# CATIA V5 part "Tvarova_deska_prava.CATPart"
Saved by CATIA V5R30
Part number: Tvarova_deska_prava
Definition: F 50_346446_46_1730
Nomenclature: F 50_346446_46_1730
Source: Unknown
Description: PART--DESC
Bounding box of the stored display mesh (mm): x -223 to 223, y -173 to 173, z -46 to 0
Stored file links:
  E:\Bakalarka\Model\Forma_v7\Tvarova_deska_prava.CATPart
  E:\Bakalarka\Model\Forma_v7\Vstrikovaci_cast.CATProduct
  E:\Bakalarka\Model\Forma_v7\Forma_Vstrikovaci_cast.CATPart
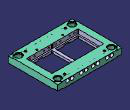
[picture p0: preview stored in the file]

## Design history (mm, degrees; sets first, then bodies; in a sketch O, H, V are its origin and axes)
Body1 "MANIFOLD_SOLID_BREP #4131" (main body)
  Solid1: solid without history
  DatumSurface1
  Sketch1 on face of Solid1, origin (0, 0, 0), H (1, 0, 0), V (0, 1, 0)
  Pocket1: profile Sketch1, direction (0, 0, -1), length 30
  Mirror1: of Pocket1, about yz-plane
  DatumCurve1 to DatumCurve9
  Sketch2 on face of Solid1, origin (0, 0, -46), H (1, 0, 0), V (0, -1, 0)
    projected line E1 (-170, 75) -> (-170, -75) from edge of DatumCurve1
    projected arc E2 centre (-165, -75) radius 5 from (-170, -75) to (-165, -80) ccw from edge of DatumCurve2
    projected line E3 (-165, -80) -> (-15, -80) from edge of DatumCurve3
    projected arc E4 centre (-15, -75) radius 5 from (-15, -80) to (-10, -75) ccw from edge of DatumCurve4
    projected line E5 (-10, -75) -> (-10, 75) from edge of DatumCurve5
    projected arc E6 centre (-15, 75) radius 5 from (-10, 75) to (-15, 80) ccw from edge of DatumCurve6
    projected line E7 (-15, 80) -> (-73.5, 80) from edge of DatumCurve7
    projected line E8 (-106.5, 80) -> (-165, 80) from edge of DatumCurve8
    projected arc E9 centre (-165, 75) radius 5 from (-165, 80) to (-170, 75) ccw from edge of DatumCurve9
    line L1 (-106.5, 80) -> (-73.5, 80)
    horizontal: L1 H
  Pocket2: profile Sketch2, direction (0, 0, 1), length 16
  Mirror2: of Pocket2, about yz-plane
  Fillet1: radius 1, on edge [face of Pocket1 | face of Mirror1]
  Fillet2: radius 1, on edge [face of Mirror1 | face of Pocket1]
  DatumCurve10 to DatumCurve12
  DatumSurface2
  DatumSurface3
  Sketch3 on face of Solid1, origin (0, 0, -46), H (1, 0, 0), V (0, -1, 0)
    line L1 (106, 80) -> (74, 80)
    line L2 (74, 80) -> (74, 113)
    line L3 (74, 113) -> (106, 113)
    line L4 (106, 113) -> (106, 80)
    reference projected line E1 (106, 80.5) -> (106, 89.5) from edge of DatumCurve12
    reference projected line E2 (106.5, 80) -> (165, 80) from edge [face of Mirror2 | face of Solid1]
    reference intersected line E3 (74.5, 105) -> (105.5, 105) from face of DatumSurface2
    reference intersected line E4 (74, 80.366) -> (74, 104.5) from face of DatumSurface3
    distance L4 E1 = 0
    distance L1 E2 = 0
    distance L3 E3 = 8
    distance L2 E4 = 0
    horizontal: L1 H, L3 H
    vertical: L2 V, L4 V
  Pocket3: profile Sketch3, direction (0, 0, 1), length 6
  Fillet3: radius 0.5, on edge [face of Pocket3 from Sketch3.L4 | end face of Pocket3]; face of Pocket3 from Sketch3.L4; face of Pocket3 from Sketch3.L3; end face of Pocket3; face of Pocket3 from Sketch3.L2
  Mirror3: of Pocket3, about yz-plane
  Fillet4: radius 0.5, on face of Mirror3 (x3); edge [face of Mirror3 | face of Solid1]
  Body2
    Solid2: solid without history
  Remove1: tool Body2
  Body3
  Remove2: tool Body3
  DatumCurve13 to DatumCurve28
  Sketch4 on face of Solid1, origin (0, 173, 0), H (-1, 0, 0), V (0, 0, 1)
    point P1 (-154.5, -14)
    point P2 (-122.5, -14)
    point P3 (-56.5, -14)
    point P4 (-24.5, -14)
    point P5 (25.5, -14)
    point P6 (57.5, -14)
    point P7 (123.5, -14)
    point P8 (155.5, -14)
    construction circle A1 centre (155.5, -14) radius 3
    construction circle A2 centre (123.5, -14) radius 3
    construction circle A3 centre (57.5, -14) radius 3
    construction circle A4 centre (25.5, -14) radius 3
    construction circle A5 centre (-24.5, -14) radius 3
    construction circle A6 centre (-56.5, -14) radius 3
    construction circle A7 centre (-122.5, -14) radius 3
    construction circle A8 centre (-154.5, -14) radius 3
    concentricity: P1 A8, P2 A7, P3 A6, P4 A5, P5 A4, P6 A3, P7 A2, P8 A1
  Sketch5 on face of Solid1, origin (0, -173, 0), H (1, 0, 0), V (0, 0, 1)
    projected point E1 (154.5, -14) from Sketch4.P1
    projected point E2 (122.5, -14) from Sketch4.P2
    projected point E3 (56.5, -14) from Sketch4.P3
    projected point E4 (24.5, -14) from Sketch4.P4
    projected point E5 (-25.5, -14) from Sketch4.P5
    projected point E6 (-57.5, -14) from Sketch4.P6
    projected point E7 (-123.5, -14) from Sketch4.P7
    projected point E8 (-155.5, -14) from Sketch4.P8
  DatumCurve29 to DatumCurve33
  DatumSurface4
  Sketch6 on face of Solid1, origin (0, 173, 0), H (-1, 0, 0), V (0, 0, 1)
    point P1 (155, -14)
    point P2 (123, -14)
    point P3 (57, -14)
    point P4 (25, -14)
    point P5 (-25, -14)
    point P6 (-57, -14)
    point P7 (-123, -14)
    point P8 (-155, -14)
    reference projected line E1 (223, 0) -> (-223, 0) from edge of DatumCurve29
    reference projected line E2 (-189, 0) -> (189, 0) from edge [face of Solid1 | face of Solid1]
    reference projected line E3 (223, 0) -> (-223, 0) from edge of DatumCurve30
    reference projected line E4 (223, 0) -> (-223, 0) from edge of DatumCurve31
    reference projected line E5 (223, 0) -> (-223, 0) from edge of DatumCurve32
    reference projected line E6 (223, 0) -> (-223, 0) from edge of DatumCurve33
    reference intersected curve E7 from face of DatumSurface4
    reference projected line E8 (223, -4) -> (223, -46) from edge [face of Solid1 | face of Solid1]
    distance P8 E1 = 14
    distance P7 E2 = 14
    distance P6 E3 = 14
    distance P5 E4 = 14
    distance P4 E5 = 14
    distance P3 E2 = 14
    distance P2 E6 = 14
    distance P1 E7 = 14
    distance P1 E8 = 68
    distance P2 P1 = 32
    distance P2 P3 = 66
    distance P3 P4 = 32
    distance P4 P5 = 50
    distance P5 P6 = 32
    distance P7 P6 = 66
    distance P7 P8 = 32
  Sketch7 on face of Solid1, origin (155, 173, -14), H (1, 0, 0), V (0, 0, -1)
    point P1 (0, 0)
    reference projected point E1 (0, 0) from Sketch6.P8
    coincidence: E1 P1
  Hole1: placed by Sketch7, at (155, 173, -14) direction (0, -1, 0), diameter 10, depth 500, V-bottom angle 120
  Sketch8 on face of Solid1, origin (123, 173, -14), H (1, 0, 0), V (0, 0, -1)
    point P1 (0, 0)
    reference projected point E1 (0, 0) from Sketch6.P7
    coincidence: E1 P1
  Hole2: placed by Sketch8, at (123, 173, -14) direction (0, -1, 0), diameter 10, depth 500, V-bottom angle 120
  Sketch9 on face of Solid1, origin (57, 173, -14), H (1, 0, 0), V (0, 0, -1)
    point P1 (0, 0)
    reference projected point E1 (0, 0) from Sketch6.P6
    coincidence: E1 P1
  Hole3: placed by Sketch9, at (57, 173, -14) direction (0, -1, 0), diameter 10, depth 500, V-bottom angle 120
  Sketch10 on face of Solid1, origin (25, 173, -14), H (1, 0, 0), V (0, 0, -1)
    point P1 (0, 0)
    reference projected point E1 (0, 0) from Sketch6.P5
    coincidence: E1 P1
  Hole4: placed by Sketch10, at (25, 173, -14) direction (0, -1, 0), diameter 10, depth 500, V-bottom angle 120
  Sketch11 on face of Solid1, origin (-25, 173, -14), H (1, 0, 0), V (0, 0, -1)
    point P1 (0, 0)
    reference projected point E1 (0, 0) from Sketch6.P4
    coincidence: E1 P1
  Hole5: placed by Sketch11, at (-25, 173, -14) direction (0, -1, 0), diameter 10, depth 500, V-bottom angle 120
  Sketch12 on face of Solid1, origin (-57, 173, -14), H (1, 0, 0), V (0, 0, -1)
    point P1 (0, 0)
    reference projected point E1 (0, 0) from Sketch6.P3
    coincidence: E1 P1
  Hole6: placed by Sketch12, at (-57, 173, -14) direction (0, -1, 0), diameter 10, depth 500, V-bottom angle 120
  Sketch13 on face of Solid1, origin (-123, 173, -14), H (1, 0, 0), V (0, 0, -1)
    point P1 (0, 0)
    reference projected point E1 (0, 0) from Sketch6.P2
    coincidence: E1 P1
  Hole7: placed by Sketch13, at (-123, 173, -14) direction (0, -1, 0), diameter 10, depth 500, V-bottom angle 120
  Sketch14 on face of Solid1, origin (-155, 173, -14), H (1, 0, 0), V (0, 0, -1)
    point P1 (0, 0)
    reference projected point E1 (0, 0) from Sketch6.P1
    coincidence: E1 P1
  Hole8: placed by Sketch14, at (-155, 173, -14) direction (0, -1, 0), diameter 10, depth 500, V-bottom angle 120
  Sketch15 on face of Solid1, origin (-155, 173, -14), H (1, 0, 0), V (0, 0, -1)
    point P1 (0, 0)
    reference projected point E1 (0, 0) from Sketch6.P1
    coincidence: E1 P1
  Hole9: placed by Sketch15, at (-155, 173, -14) direction (0, -1, 0), diameter 12.376, depth 12, V-bottom angle 120, threaded "M14x1.5", thread diameter 14, thread depth 10, pitch 1.5
  Sketch16 on face of Solid1, origin (-123, 173, -14), H (1, 0, 0), V (0, 0, -1)
    point P1 (0, 0)
    reference projected point E1 (0, 0) from Sketch6.P2
    coincidence: E1 P1
  Hole10: placed by Sketch16, at (-123, 173, -14) direction (0, -1, 0), diameter 12.376, depth 12, V-bottom angle 120, threaded "M14x1.5", thread diameter 14, thread depth 10, pitch 1.5
  Sketch17 on face of Solid1, origin (-57, 173, -14), H (1, 0, 0), V (0, 0, -1)
    point P1 (0, 0)
    reference projected point E1 (0, 0) from Sketch6.P3
    coincidence: E1 P1
  Hole11: placed by Sketch17, at (-57, 173, -14) direction (0, -1, 0), diameter 12.376, depth 12, V-bottom angle 120, threaded "M14x1.5", thread diameter 14, thread depth 10, pitch 1.5
  Sketch18 on face of Solid1, origin (-25, 173, -14), H (1, 0, 0), V (0, 0, -1)
    point P1 (0, 0)
    reference projected point E1 (0, 0) from Sketch6.P4
    coincidence: E1 P1
  Hole12: placed by Sketch18, at (-25, 173, -14) direction (0, -1, 0), diameter 12.376, depth 12, V-bottom angle 120, threaded "M14x1.5", thread diameter 14, thread depth 10, pitch 1.5
  Sketch19 on face of Solid1, origin (25, 173, -14), H (1, 0, 0), V (0, 0, -1)
    point P1 (0, 0)
    reference projected point E1 (0, 0) from Sketch6.P5
    coincidence: E1 P1
  Hole13: placed by Sketch19, at (25, 173, -14) direction (0, -1, 0), diameter 12.376, depth 12, V-bottom angle 120, threaded "M14x1.5", thread diameter 14, thread depth 10, pitch 1.5
  Sketch20 on face of Solid1, origin (57, 173, -14), H (1, 0, 0), V (0, 0, -1)
    point P1 (0, 0)
    reference projected point E1 (0, 0) from Sketch6.P6
    coincidence: E1 P1
  Hole14: placed by Sketch20, at (57, 173, -14) direction (0, -1, 0), diameter 12.376, depth 12, V-bottom angle 120, threaded "M14x1.5", thread diameter 14, thread depth 10, pitch 1.5
  Sketch21 on face of Solid1, origin (155, 173, -14), H (1, 0, 0), V (0, 0, -1)
    point P1 (0, 0)
    reference projected point E1 (0, 0) from Sketch6.P8
    coincidence: E1 P1
  Hole15: placed by Sketch21, at (155, 173, -14) direction (0, -1, 0), diameter 12.376, depth 12, V-bottom angle 120, threaded "M14x1.5", thread diameter 14, thread depth 10, pitch 1.5
  Sketch22 on face of Solid1, origin (123, 173, -14), H (1, 0, 0), V (0, 0, -1)
    point P1 (0, 0)
    reference projected point E1 (0, 0) from Sketch6.P7
    coincidence: E1 P1
  Hole16: placed by Sketch22, at (123, 173, -14) direction (0, -1, 0), diameter 12.376, depth 12, V-bottom angle 120, threaded "M14x1.5", thread diameter 14, thread depth 10, pitch 1.5
  Sketch23 on face of Solid1, origin (0, -173, 0), H (1, 0, 0), V (0, 0, 1)
    projected point E1 (155, -14) from Sketch6.P8
    projected point E2 (123, -14) from Sketch6.P7
    projected point E3 (57, -14) from Sketch6.P6
    projected point E4 (25, -14) from Sketch6.P5
    projected point E5 (-25, -14) from Sketch6.P4
    projected point E6 (-57, -14) from Sketch6.P3
    projected point E7 (-123, -14) from Sketch6.P2
    projected point E8 (-155, -14) from Sketch6.P1
  Sketch24 on face of Solid1, origin (-155, -173, -14), H (1, 0, 0), V (0, 0, 1)
    point P1 (0, 0)
    reference projected point E1 (0, 0) from vertex of Sketch23.E8
    coincidence: E1 P1
  Hole17: placed by Sketch24, at (-155, -173, -14) direction (0, 1, 0), diameter 12.376, depth 12, V-bottom angle 120, threaded "M14x1.5", thread diameter 14, thread depth 10, pitch 1.5
  Sketch25 on face of Solid1, origin (-123, -173, -14), H (1, 0, 0), V (0, 0, 1)
    point P1 (0, 0)
    reference projected point E1 (0, 0) from vertex of Sketch23.E7
    coincidence: E1 P1
  Hole18: placed by Sketch25, at (-123, -173, -14) direction (0, 1, 0), diameter 12.376, depth 12, V-bottom angle 120, threaded "M14x1.5", thread diameter 14, thread depth 10, pitch 1.5
  Sketch26 on face of Solid1, origin (-57, -173, -14), H (1, 0, 0), V (0, 0, 1)
    point P1 (0, 0)
    reference projected point E1 (0, 0) from vertex of Sketch23.E6
    coincidence: E1 P1
  Hole19: placed by Sketch26, at (-57, -173, -14) direction (0, 1, 0), diameter 12.376, depth 12, V-bottom angle 120, threaded "M14x1.5", thread diameter 14, thread depth 10, pitch 1.5
  Sketch27 on face of Solid1, origin (-25, -173, -14), H (1, 0, 0), V (0, 0, 1)
    point P1 (0, 0)
    reference projected point E1 (0, 0) from vertex of Sketch23.E5
    coincidence: E1 P1
  Hole20: placed by Sketch27, at (-25, -173, -14) direction (0, 1, 0), diameter 12.376, depth 12, V-bottom angle 120, threaded "M14x1.5", thread diameter 14, thread depth 10, pitch 1.5
  Sketch28 on face of Solid1, origin (25, -173, -14), H (1, 0, 0), V (0, 0, 1)
    point P1 (0, 0)
    reference projected point E1 (0, 0) from vertex of Sketch23.E4
    coincidence: E1 P1
  Hole21: placed by Sketch28, at (25, -173, -14) direction (0, 1, 0), diameter 12.376, depth 12, V-bottom angle 120, threaded "M14x1.5", thread diameter 14, thread depth 10, pitch 1.5
  Sketch29 on face of Solid1, origin (57, -173, -14), H (1, 0, 0), V (0, 0, 1)
    point P1 (0, 0)
    reference projected point E1 (0, 0) from vertex of Sketch23.E3
    coincidence: E1 P1
  Hole22: placed by Sketch29, at (57, -173, -14) direction (0, 1, 0), diameter 12.376, depth 12, V-bottom angle 120, threaded "M14x1.5", thread diameter 14, thread depth 10, pitch 1.5
  Sketch30 on face of Solid1, origin (123, -173, -14), H (1, 0, 0), V (0, 0, 1)
    point P1 (0, 0)
    reference projected point E1 (0, 0) from vertex of Sketch23.E2
    coincidence: E1 P1
  Hole23: placed by Sketch30, at (123, -173, -14) direction (0, 1, 0), diameter 12.376, depth 12, V-bottom angle 120, threaded "M14x1.5", thread diameter 14, thread depth 10, pitch 1.5
  Sketch31 on face of Solid1, origin (155, -173, -14), H (1, 0, 0), V (0, 0, 1)
    point P1 (0, 0)
    reference projected point E1 (0, 0) from vertex of Sketch23.E1
    coincidence: E1 P1
  Hole24: placed by Sketch31, at (155, -173, -14) direction (0, 1, 0), diameter 12.376, depth 12, V-bottom angle 120, threaded "M14x1.5", thread diameter 14, thread depth 10, pitch 1.5
  Sketch32 on face of Solid1, origin (0, -173, 0), H (1, 0, 0), V (0, 0, 1)
    circle A1 centre (155, -14) radius 12.5
    point P1 (155, -14)
    circle A2 centre (123, -14) radius 12.5
    circle A3 centre (57, -14) radius 12.5
    circle A4 centre (25, -14) radius 12.5
    circle A5 centre (-25, -14) radius 12.5
    circle A6 centre (-57, -14) radius 12.5
    circle A7 centre (-123, -14) radius 12.5
    circle A8 centre (-155, -14) radius 12.5
    reference projected line E1 (-189, 0) -> (189, 0) from edge [face of Solid1 | face of Solid1]
    reference projected line E2 (-223, -4) -> (-223, -42) from edge [face of Solid1 | face of Solid1]
    radius A8 = 12.5
    radius A7 = 12.5
    radius A6 = 12.5
    radius A5 = 12.5
    radius A4 = 12.5
    radius A3 = 12.5
    radius A2 = 12.5
    radius A1 = 12.5
    distance P1 E1 = 14
    distance A2 E1 = 1.5
    distance A3 E1 = 26.5
    distance A4 E1 = 1.5
    distance A5 E1 = 26.5
    distance A6 E1 = 1.5
    distance A7 E1 = 1.5
    distance A8 E1 = 26.5
    distance A8 E2 = 80.5
    distance A7 A8 = 7
    distance A6 A7 = 41
    distance A5 A6 = 7
    distance A5 A4 = 50
    distance A3 A4 = 7
    distance A3 A2 = 66
    distance A2 A1 = 32
  Pocket4: profile Sketch32, direction (0, 1, 0), length 25
  Mirror4: of Pocket4, about zx-plane
  Sketch33 on face of Mirror4, origin (0, 148, 0), H (-1, 0, 0), V (0, 0, 1)
    projected point E1 (-155, -14) from vertex of Sketch23.E1
    projected point E2 (-123, -14) from vertex of Sketch23.E2
    projected point E3 (-57, -14) from vertex of Sketch23.E3
    projected point E4 (-25, -14) from vertex of Sketch23.E4
    projected point E5 (25, -14) from vertex of Sketch23.E5
    projected point E6 (57, -14) from vertex of Sketch23.E6
    projected point E7 (123, -14) from vertex of Sketch23.E7
    projected point E8 (155, -14) from vertex of Sketch23.E8
  Sketch34 on face of Mirror4, origin (-155, 148, -14), H (1, 0, 0), V (0, 0, -1)
    point P1 (0, 0)
    reference projected point E1 (0, 0) from vertex of Sketch33.E8
    coincidence: E1 P1
  Hole25: placed by Sketch34, at (-155, 148, -14) direction (0, -1, 0), diameter 12.376, depth 12, V-bottom angle 120, threaded "M14x1.5", thread diameter 14, thread depth 10, pitch 1.5
  Sketch35 on face of Mirror4, origin (-123, 148, -14), H (1, 0, 0), V (0, 0, -1)
    point P1 (0, 0)
    reference projected point E1 (0, 0) from vertex of Sketch33.E7
    coincidence: E1 P1
  Hole26: placed by Sketch35, at (-123, 148, -14) direction (0, -1, 0), diameter 12.376, depth 12, V-bottom angle 120, threaded "M14x1.5", thread diameter 14, thread depth 10, pitch 1.5
  Sketch36 on face of Mirror4, origin (-57, 148, -14), H (1, 0, 0), V (0, 0, -1)
    point P1 (0, 0)
    reference projected point E1 (0, 0) from vertex of Sketch33.E6
    coincidence: E1 P1
  Hole27: placed by Sketch36, at (-57, 148, -14) direction (0, -1, 0), diameter 12.376, depth 12, V-bottom angle 120, threaded "M14x1.5", thread diameter 14, thread depth 10, pitch 1.5
  Sketch37 on face of Mirror4, origin (-25, 148, -14), H (1, 0, 0), V (0, 0, -1)
    point P1 (0, 0)
    reference projected point E1 (0, 0) from vertex of Sketch33.E5
    coincidence: E1 P1
  Hole28: placed by Sketch37, at (-25, 148, -14) direction (0, -1, 0), diameter 12.376, depth 12, V-bottom angle 120, threaded "M14x1.5", thread diameter 14, thread depth 10, pitch 1.5
  Sketch38 on face of Mirror4, origin (25, 148, -14), H (1, 0, 0), V (0, 0, -1)
    point P1 (0, 0)
    reference projected point E1 (0, 0) from vertex of Sketch33.E4
    coincidence: E1 P1
  Hole29: placed by Sketch38, at (25, 148, -14) direction (0, -1, 0), diameter 12.376, depth 12, V-bottom angle 120, threaded "M14x1.5", thread diameter 14, thread depth 10, pitch 1.5
  Sketch39 on face of Mirror4, origin (57, 148, -14), H (1, 0, 0), V (0, 0, -1)
    point P1 (0, 0)
    reference projected point E1 (0, 0) from vertex of Sketch33.E3
    coincidence: E1 P1
  Hole30: placed by Sketch39, at (57, 148, -14) direction (0, -1, 0), diameter 12.376, depth 12, V-bottom angle 120, threaded "M14x1.5", thread diameter 14, thread depth 10, pitch 1.5
  Sketch40 on face of Mirror4, origin (123, 148, -14), H (1, 0, 0), V (0, 0, -1)
    point P1 (0, 0)
    reference projected point E1 (0, 0) from vertex of Sketch33.E2
    coincidence: E1 P1
  Hole31: placed by Sketch40, at (123, 148, -14) direction (0, -1, 0), diameter 12.376, depth 12, V-bottom angle 120, threaded "M14x1.5", thread diameter 14, thread depth 10, pitch 1.5
  Sketch41 on face of Mirror4, origin (155, 148, -14), H (1, 0, 0), V (0, 0, -1)
    point P1 (0, 0)
    reference projected point E1 (0, 0) from vertex of Sketch33.E1
    coincidence: E1 P1
  Hole32: placed by Sketch41, at (155, 148, -14) direction (0, -1, 0), diameter 12.376, depth 12, V-bottom angle 120, threaded "M14x1.5", thread diameter 14, thread depth 10, pitch 1.5
  Sketch42 on end face of Pocket4, origin (0, -148, 0), H (1, 0, 0), V (0, 0, 1)
    projected point E1 (155, -14) from vertex of Sketch33.E1
    projected point E2 (123, -14) from vertex of Sketch33.E2
    projected point E3 (57, -14) from vertex of Sketch33.E3
    projected point E4 (25, -14) from vertex of Sketch33.E4
    projected point E5 (-25, -14) from vertex of Sketch33.E5
    projected point E6 (-57, -14) from vertex of Sketch33.E6
    projected point E7 (-123, -14) from vertex of Sketch33.E7
    projected point E8 (-155, -14) from vertex of Sketch33.E8
  Sketch43 on end face of Pocket4, origin (-155, -148, -14), H (1, 0, 0), V (0, 0, 1)
    point P1 (0, 0)
    reference projected point E1 (0, 0) from vertex of Sketch42.E8
    coincidence: E1 P1
  Hole33: placed by Sketch43, at (-155, -148, -14) direction (0, 1, 0), diameter 12.376, depth 12, V-bottom angle 120, threaded "M14x1.5", thread diameter 14, thread depth 10, pitch 1.5
  Sketch44 on end face of Pocket4, origin (-123, -148, -14), H (1, 0, 0), V (0, 0, 1)
    point P1 (0, 0)
    reference projected point E1 (0, 0) from vertex of Sketch42.E7
    coincidence: E1 P1
  Hole34: placed by Sketch44, at (-123, -148, -14) direction (0, 1, 0), diameter 12.376, depth 12, V-bottom angle 120, threaded "M14x1.5", thread diameter 14, thread depth 10, pitch 1.5
  Sketch45 on end face of Pocket4, origin (-57, -148, -14), H (1, 0, 0), V (0, 0, 1)
    point P1 (0, 0)
    reference projected point E1 (0, 0) from vertex of Sketch42.E6
    coincidence: E1 P1
  Hole35: placed by Sketch45, at (-57, -148, -14) direction (0, 1, 0), diameter 12.376, depth 12, V-bottom angle 120, threaded "M14x1.5", thread diameter 14, thread depth 10, pitch 1.5
  Sketch46 on end face of Pocket4, origin (-25, -148, -14), H (1, 0, 0), V (0, 0, 1)
    point P1 (0, 0)
    reference projected point E1 (0, 0) from vertex of Sketch42.E5
    coincidence: E1 P1
  Hole36: placed by Sketch46, at (-25, -148, -14) direction (0, 1, 0), diameter 12.376, depth 12, V-bottom angle 120, threaded "M14x1.5", thread diameter 14, thread depth 10, pitch 1.5
  Sketch47 on end face of Pocket4, origin (25, -148, -14), H (1, 0, 0), V (0, 0, 1)
    point P1 (0, 0)
    reference projected point E1 (0, 0) from vertex of Sketch42.E4
    coincidence: E1 P1
  Hole37: placed by Sketch47, at (25, -148, -14) direction (0, 1, 0), diameter 12.376, depth 12, V-bottom angle 120, threaded "M14x1.5", thread diameter 14, thread depth 10, pitch 1.5
  Sketch48 on end face of Pocket4, origin (57, -148, -14), H (1, 0, 0), V (0, 0, 1)
    point P1 (0, 0)
    reference projected point E1 (0, 0) from vertex of Sketch42.E3
    coincidence: E1 P1
  Hole38: placed by Sketch48, at (57, -148, -14) direction (0, 1, 0), diameter 12.376, depth 12, V-bottom angle 120, threaded "M14x1.5", thread diameter 14, thread depth 10, pitch 1.5
  Sketch49 on end face of Pocket4, origin (123, -148, -14), H (1, 0, 0), V (0, 0, 1)
    point P1 (0, 0)
    reference projected point E1 (0, 0) from vertex of Sketch42.E2
    coincidence: E1 P1
  Hole39: placed by Sketch49, at (123, -148, -14) direction (0, 1, 0), diameter 12.376, depth 12, V-bottom angle 120, threaded "M14x1.5", thread diameter 14, thread depth 10, pitch 1.5
  Sketch50 on end face of Pocket4, origin (155, -148, -14), H (1, 0, 0), V (0, 0, 1)
    point P1 (0, 0)
    reference projected point E1 (0, 0) from vertex of Sketch42.E1
    coincidence: E1 P1
  Hole40: placed by Sketch50, at (155, -148, -14) direction (0, 1, 0), diameter 12.376, depth 12, V-bottom angle 120, threaded "M14x1.5", thread diameter 14, thread depth 10, pitch 1.5
  DatumCurve34 to DatumCurve39
  Sketch51 on face of Solid1, origin (0, -173, 0), H (1, 0, 0), V (0, 0, 1)
    reference projected curve E2 from edge of DatumCurve35
    point P3 (25.3953, -46)
    point P4 (44.6047, -46)
    reference projected curve E3 from edge of DatumCurve36
    point P5 (-45.1047, -46)
    reference projected curve E4 from edge of DatumCurve37
    point P8 (-135.3953, -46)
    arc A1 centre (143.5, -54) radius 12.5 from (153.1047, -46) to (133.8953, -46) ccw
    arc A2 centre (35, -54) radius 12.5 from (44.6047, -46) to (25.3953, -46) ccw
    point P11 (44.6047, -46)
    arc A3 centre (-35.5, -54) radius 12.5 from (-25.8953, -46) to (-45.1047, -46) ccw
    point P13 (-45.1047, -46)
    point P14 (-45.1048, -46.0001)
    arc A4 centre (-145, -54) radius 12.5 from (-135.3953, -46) to (-154.6047, -46) ccw
    point P16 (-135.3953, -46)
    line L1 (-154.6047, -46) -> (-135.3953, -46)
    point P17 (-135.3953, -46)
    reference projected line E5 (-135.3953, -46) -> (-45.1047, -46) from edge of DatumCurve39
    line L2 (-25.8953, -46) -> (-45.1047, -46)
    line L3 (25.3953, -46) -> (44.6047, -46)
    point P18 (25.3953, -46)
    line L4 (133.8953, -46) -> (153.1047, -46)
    radius A4 = 12.5
    radius A3 = 12.5
    distance P13 P5 = 0
    radius A2 = 12.5
    radius A1 = 12.5
    angle L1 E5 = 180
    distance L3 P3 = 0
    distance P11 P4 V = 0
    distance P16 P8 = 0
    coincidence: P11 E2, P13 E3, A3 P14, P14 E3, P17 E4, P18 A2
    horizontal: L2 H, L4 H
  Pocket5: profile Sketch51, direction (0, 1, 0), length 18
  Body4 "Result of TapHole"
    Solid3: linked copy from another document
  Assemble1 "TapHoleCapScrew_E1200_2.3": tool Body4
  Body5 "Result of TapHole"
    Solid4: linked copy from another document
  Assemble2 "TapHoleCapScrew_E1200_2.4": tool Body5
  Sketch52 on face of Solid1, origin (0, 0, -46), H (1, 0, 0), V (0, -1, 0)
    point P1 (101.5, 148.1573)
    point P2 (77.5, 148.1573)
  Sketch53 on face of Solid1, origin (77.5, -148.1573, -46), H (1, 0, 0), V (0, -1, 0)
    point P1 (0, 0)
    reference projected point E1 (0, 0) from Sketch52.P2
    coincidence: E1 P1
  Hole41: placed by Sketch53, at (77.5, -148.1573, -46) direction (0, 0, 1), diameter 3.242, depth 13, V-bottom angle 120, threaded "M4", thread diameter 4, thread depth 11, pitch 0.7
  Sketch54 on face of Solid1, origin (101.5, -148.1573, -46), H (1, 0, 0), V (0, -1, 0)
    point P1 (0, 0)
    reference projected point E1 (0, 0) from Sketch52.P1
    coincidence: E1 P1
  Hole42: placed by Sketch54, at (101.5, -148.1573, -46) direction (0, 0, 1), diameter 3.242, depth 13, V-bottom angle 120, threaded "M4", thread diameter 4, thread depth 11, pitch 0.7
  Body6 "MANIFOLD_SOLID_BREP #197"
    Solid5: solid without history
  Remove3: tool Body6
  Body7 "MANIFOLD_SOLID_BREP #197"
    Solid6: solid without history
  Remove4: tool Body7
  DatumCurve40 to DatumCurve42
  Sketch55 on face of Solid1, origin (0, 0, -46), H (1, 0, 0), V (0, -1, 0)
    projected line E1 (-223, -139) -> (-189, -173) from edge of DatumCurve40
    projected line E2 (-223, -173) -> (-189, -173) from edge of DatumCurve41
    projected line E3 (-223, -139) -> (-223, -173) from edge of DatumCurve42
  Pocket6: profile Sketch55, direction (0, 0, 1), length 4
  Body8 "E 1032_12x120"
    Solid7: solid without history
  Remove5: tool Body8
